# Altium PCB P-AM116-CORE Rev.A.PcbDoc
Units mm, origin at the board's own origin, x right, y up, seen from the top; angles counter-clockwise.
Board outline 129.17 x 91.46 mm, 2 copper layers (Top Layer, Bottom Layer); 0 components, 59 nets, 0 pads, 0 vias.
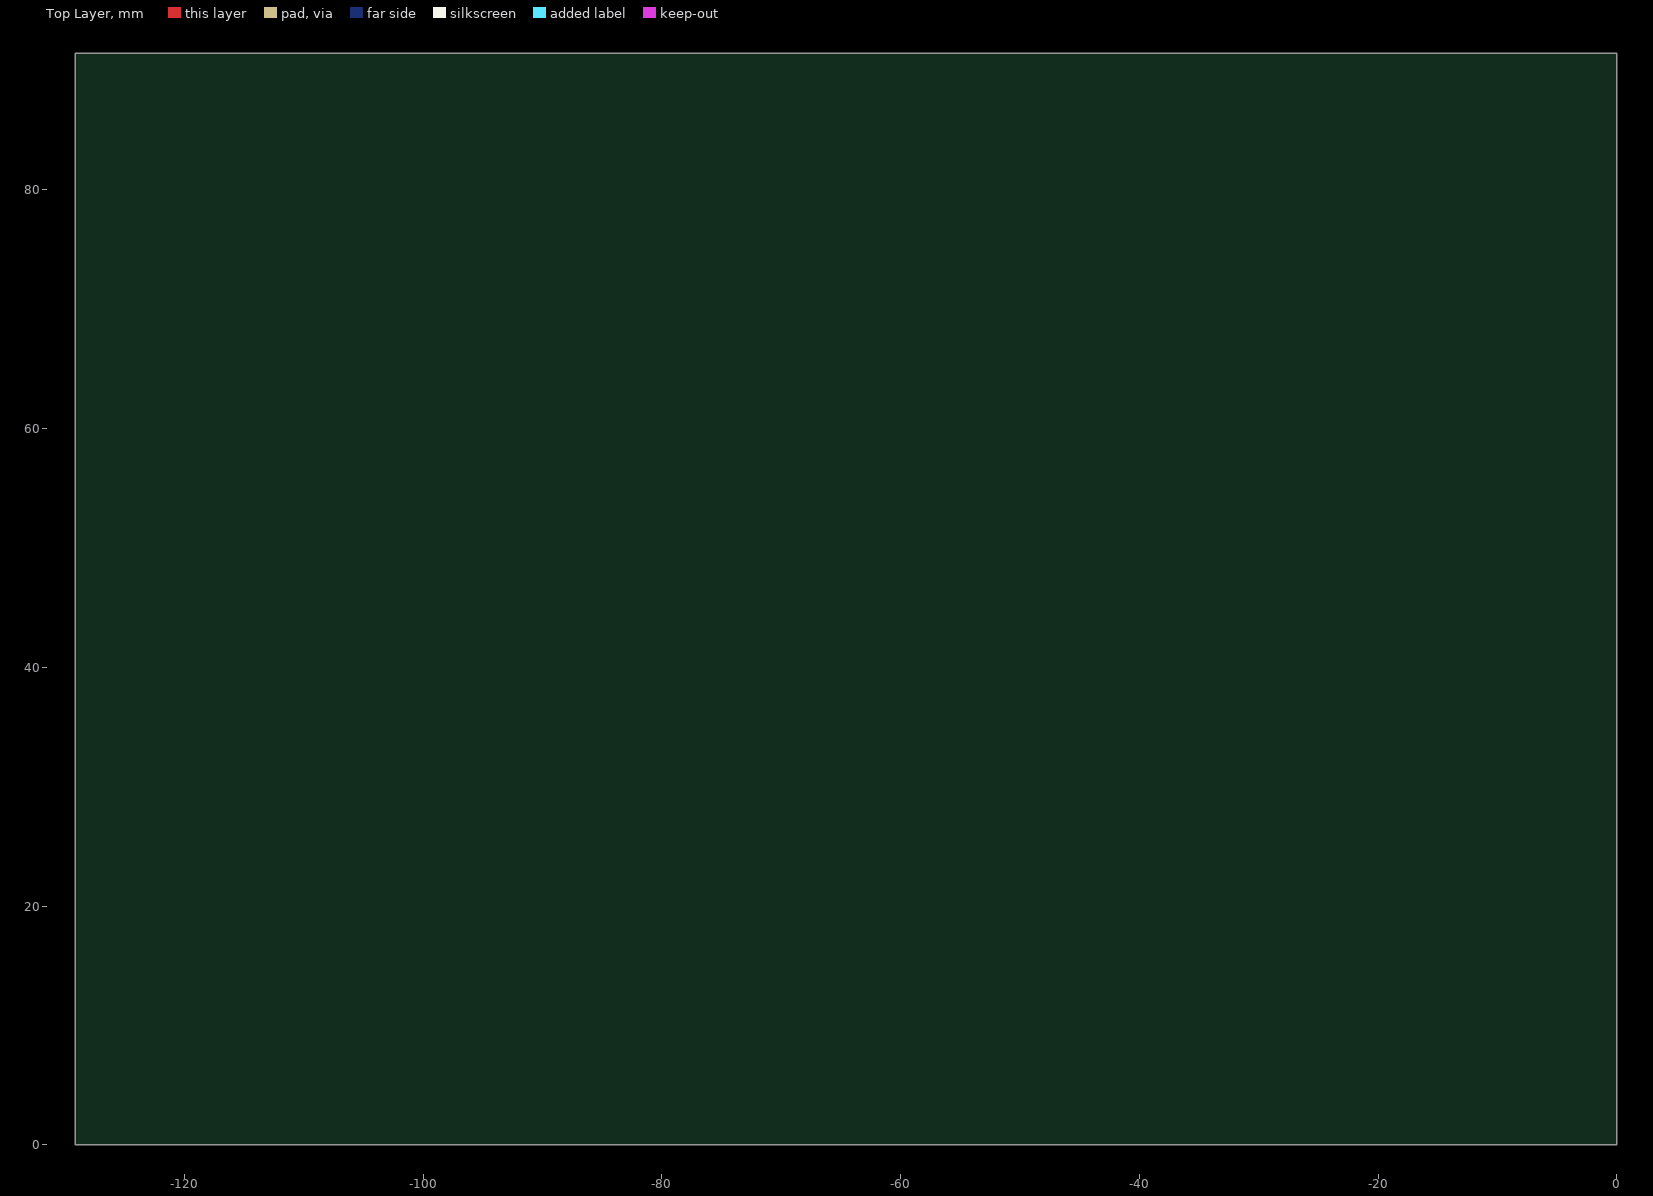
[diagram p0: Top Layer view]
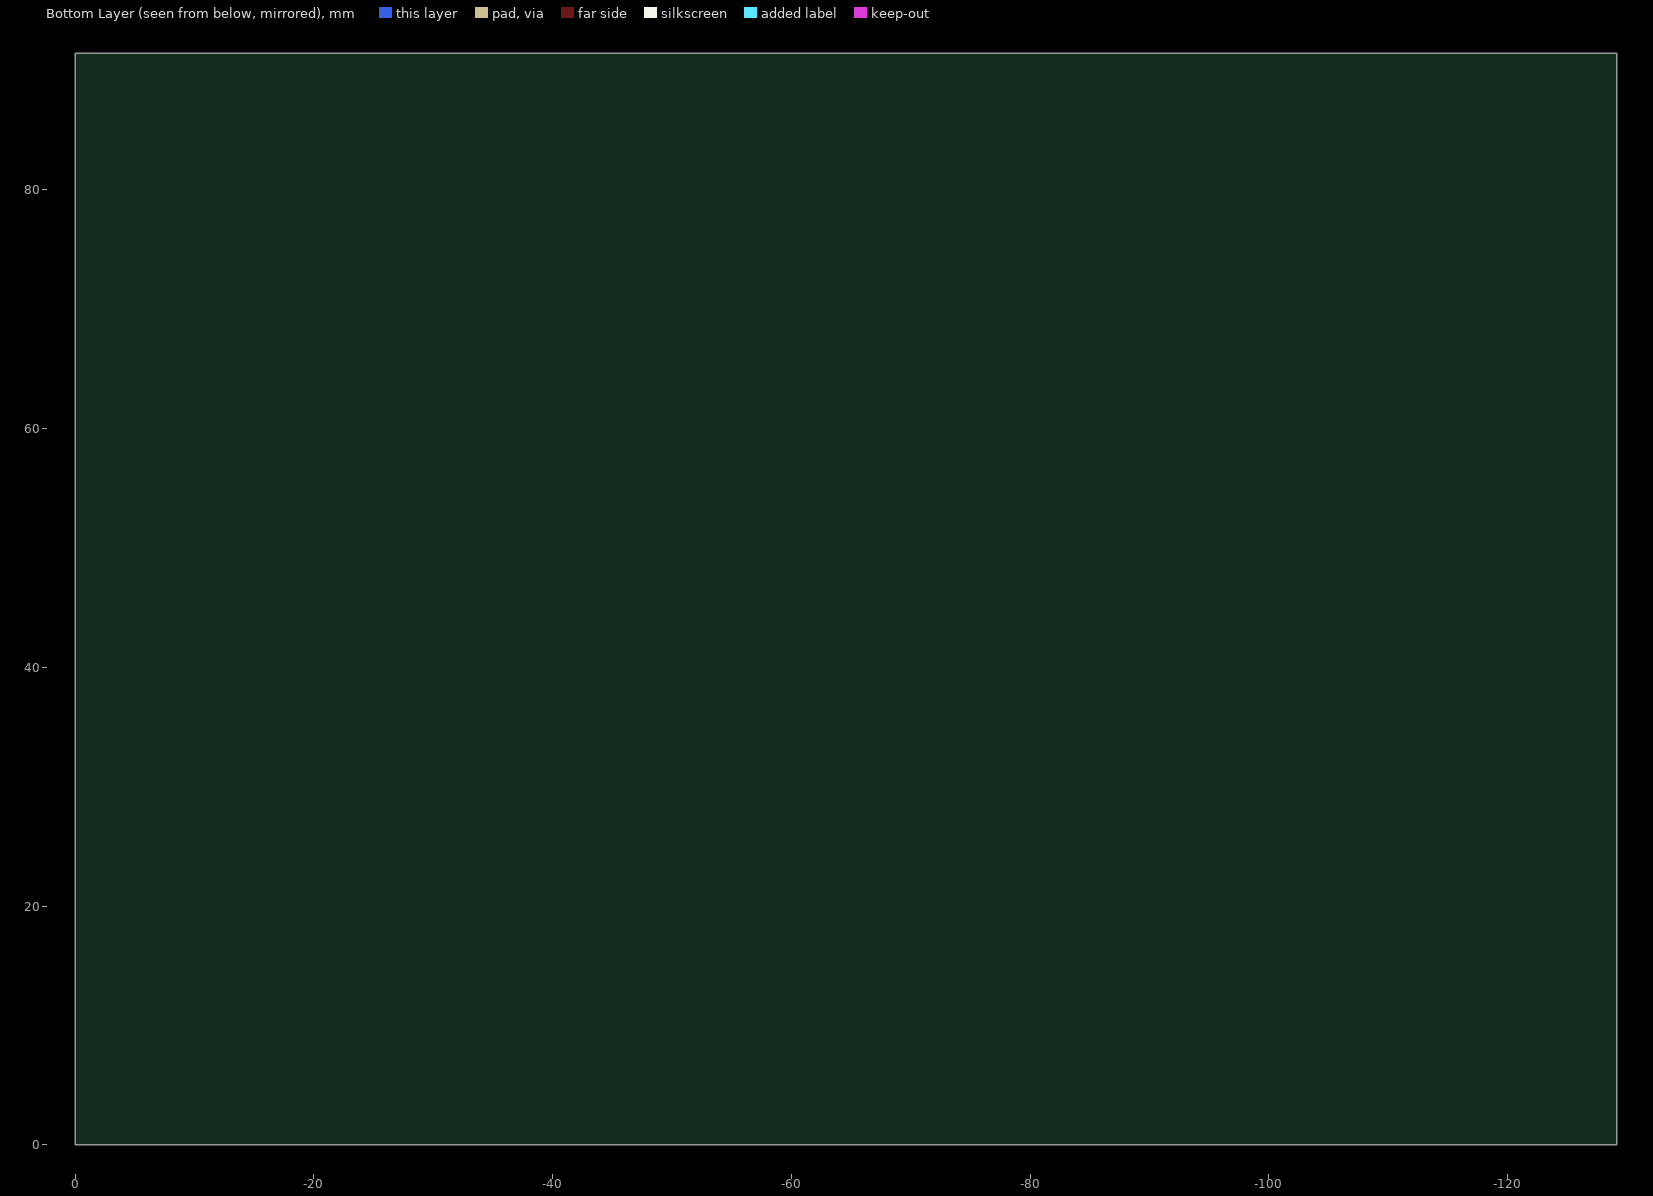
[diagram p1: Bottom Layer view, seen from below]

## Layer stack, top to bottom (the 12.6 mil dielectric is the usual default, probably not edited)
Top Solder: solder mask 0.0102, Solder Resist, Dk 3.5
Top Layer: signal copper 0.0356
Dielectric1: core 0.32, FR-4, Dk 4.8
Bottom Layer: signal copper 0.0356
Bottom Solder: solder mask 0.0102, Solder Resist, Dk 3.5

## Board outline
-129.165,0 -129.165,91.46 0,91.46 0,0

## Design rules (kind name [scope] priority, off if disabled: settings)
Clearance Clearance_Keepout [OnLayer('Keep-Out Layer')] p1: gap=0.508
Clearance Clearance_Manual [OnLayer('Bottom Layer') and IsSMTPin vs IsPadHoleValid>   (  HasFootprint('PAD-35/50') or   HasFootprint('HOLE-3.2') or  HasFootprint('HOLE-3.2 - Screw') or   HasFootprint('HOLE4.22-SMT') or   HasFootprint('Mou Hole-300D450W310H-SMD') or    HasFootprint('AW6748') or  HasFootprint('IDCS80P500W-20X2-F')  )] p2: gap=1.27
Clearance Clearance_Via2Via [IsVia vs IsVia] p3: gap=0.152
Clearance Clearance_Poly2All [InPoly] p4: gap=0.381
Clearance Clearance_TP [HasFootprint('PAD-40') vs HasFootprint('PAD-40')] p5: gap=1.27
Clearance [All] p6: gap=0.152
ComponentClearance [All] p1: gap=0 collisioncheckmode=3 verticalgap=0 showdistances=FALSE
DiffPairsRouting [All] p1: maxlimit=0.203 minlimit=0.203 mostfreqgap=0.203 toplayer_minwidth=0.14 toplayer_maxwidth=0.14 toplayer_prefwidth=0.14 bottomlayer_minwidth=0.14 bottomlayer_maxwidth=0.14 bottomlayer_prefwidth=0.14 maxuncoupledlength=12.7
HoleSize [All] p1: absolutevalues=TRUE maxlimit=25.4 minlimit=0.025 maxpercent=80.000 minpercent=20.000
MinimumSolderMaskSliver [All] p1: minsoldermaskwidth=0.025
PlaneClearance PlaneClearance_Full [IsVia] p1: clearance=0.229
PlaneClearance [All] p2: clearance=0.508
PlaneConnect PlaneConnect_Full [IsVia] p1: planeconnectstyle=Direct reliefexpansion=0.508 reliefentries=4 reliefconductorwidth=0.254 reliefairgap=0.254
PlaneConnect [All] p2: planeconnectstyle=Relief reliefexpansion=0.254 reliefentries=4 reliefconductorwidth=0.381 reliefairgap=0.254
PolygonConnect PolygonConnect_SMDHole [HasFootprint('Mou Hole-300D450W310H-SMD') or HasFootprint('Mou Hole-373D600H-SMD')] p1: connectstyle=Relief reliefconductorwidth=2.032 reliefentries=4 polygonreliefangle="45 Angle" airgapwidth=0.508
PolygonConnect PolygonConnect_Full [IsVia or   HasFootprint('PAD-40') or   HasFootprint('PAD-35/50') or  HasFootprint('HOLE-3.2') or   HasFootprint('HOLE-3.2 - Screw')] p2: connectstyle=Direct reliefconductorwidth=0.254 reliefentries=4 polygonreliefangle="90 Angle" airgapwidth=0.254
PolygonConnect [All] p3: connectstyle=Relief reliefconductorwidth=0.381 reliefentries=4 polygonreliefangle="90 Angle" airgapwidth=0.381
RoutingVias [All] p1: holewidth=0.305 width=0.508 viastyle="Through Hole" minholewidth=0.305 minwidth=0.508 maxholewidth=0.305 maxwidth=0.508
SilkToSilkClearance [All] p1: silktosilkclearance=0
SilkToSolderMaskClearance [IsPad] p1: minsilkscreentomaskgap=0 clearancetoexposedcopper=TRUE
SolderMaskExpansion [All] p1: expansion=0.102
Width [All] p1: maxlimit=2.54 minlimit=0.152 preferedwidth=0.152
22 further rules are at their usual default settings.

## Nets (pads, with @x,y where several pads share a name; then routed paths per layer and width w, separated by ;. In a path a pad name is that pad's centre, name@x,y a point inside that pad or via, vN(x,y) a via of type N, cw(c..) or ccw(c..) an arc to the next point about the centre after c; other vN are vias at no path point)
3.3V: 
3.3VA: 
3.3VA_MM32L: 
5V: 
5V/3.3VA_MICROP: 
ADC: 
ADC0/IO19_MICROP: 
ADC1/IO20_MICROP: 
AGND: 
BEEP: 
BOOT0: 
CS/GPIO7_MINIP: 
CTS/IO13_MICROP: 
DAC/IO21_MICROP: 
GPIO5_J5: 
GPIO6_J5: 
GPIO7_J5: 
GPIO8_J5: 
GPIO8_MINIP: 
GPIO9_J5: 
GPIO10_J5: 
GPIO11_J5: 
GPIO12_J5: 
GPIO13_J5: 
GPIO14_J5: 
GPIO14_MINIP: 
GPIO15_J5: 
GPIO16_J5: 
GPIO16_MINIP: 
GPIO17_J5: 
GPIO18_J5: 
GPIO18_MINIP: 
GPIO19_J5: 
GPIO20_J5: 
"IO 1_MICROP": 
"IO 2_MICROP": 
"IO 3_MICROP": 
LED0: 
LED1: 
LM75_SCL: 
LM75_SDA: 
MISO/GPIO9_MINIP: 
MOSI/GPIO15_MINIP: 
NetBZ1_1: 
NetC3_1: 
NetC4_1: 
NetC10_1: 
NetJ14_2: 
NetJ14_3: 
NetLED0_2: 
NetLED1_2: 
NetLED2_1: 
NetQ1_1: 
PA3/UART2_RX: 
PA5/SPI1_SCK: 
PWM2/IO7_MICROP: 
R\E\S\E\T\: 
SCL: 
SDA: 

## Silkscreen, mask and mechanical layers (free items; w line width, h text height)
Mechanical 1:
  lines w0.013: -129.165,4 -129.165,0 0,0 0,4 ; -129.165,87.46 -129.165,91.46 0,91.46 0,87.46
  lines w0.127: -131.705,3.998 -129.648,3.998 ; -131.705,45.728 -129.648,45.728 ; -131.705,87.458 -129.648,87.458 ; -130.333,3.49 -129.648,3.998 ; -130.333,4.506 -129.648,3.998 ; -130.333,45.22 -129.648,45.728 ; -130.333,46.236 -129.648,45.728 ; -130.333,86.95 -129.648,87.458 ; -130.333,87.966 -129.648,87.458 ; -65.077,93.726 -64.569,93.04 ; -64.569,95.098 -64.569,93.04 ; -64.061,93.726 -64.569,93.04 ; -129.165,45.73 -64.583,45.73 ; -129.165,45.73 -129.165,87.46 -64.583,87.46 ; -129.165,45.73 -129.165,4 -64.583,4 ; -129.165,45.73 -64.583,45.73 ; -64.583,4 0,4 0,45.73 ; -64.583,4 -64.583,45.73 ; -64.583,4 -64.583,45.73 ; -64.583,45.73 0,45.73 ; -64.583,45.73 -64.583,87.46 ; -64.583,45.73 -64.583,87.46 ; -64.583,45.73 0,45.73 ; -64.583,87.46 0,87.46 0,45.73
  text "VCUT" at -65.567,100.558 h1.52 r270
  text "VCUT" at -137.165,86.46 h1.52
  text "VCUT" at -137.293,45.118 h1.52
  text "VCUT" at -137.395,3.259 h1.52
Mechanical 2:
  drawing of 637 lines, arcs and shapes, not listed
  text "PCB加工工艺要求" at 70.723,109.689 h7.11
  text "mm x" at 50.327,104.965 h2.54
  text "mm" at 65.821,104.965 h2.54
  text "129.16" at 41.818,104.736 h2.54
  text "91.46" at 57.312,104.736 h2.54
  text "IPC-600E   IPC-6011/12" at 95.234,104.711 h2.54
  text "IPC-Ⅱ" at 129.143,104.686 h2.54
  text "IPC-Ⅲ" at 141.843,104.686 h2.54
  text "尺寸" at 27.764,104.257 h3.81
  text "验收标准" at 78.564,104.257 h3.81
  text "FR4 TG140" at 45.704,99.631 h2.54
  text "FR4 TG170" at 68.564,99.631 h2.54
  text "生益有胶材料" at 91.424,99.631 h2.54
  text "MEGTRON6" at 114.284,99.631 h2.54
  text "其他：" at 137.144,99.631 h2.54
  text "板材" at 27.728,99.172 h3.81
  text "单面" at 45.704,94.551 h2.54
  text "2" at 63.484,94.551 h2.54
  text "4" at 81.264,94.551 h2.54
  text "6" at 99.044,94.551 h2.54
  text "8" at 116.824,94.551 h2.54
  text "10" at 134.604,94.551 h2.54
  text "板层" at 27.728,94.087 h3.81
  text "0.4mm" at 45.704,89.471 h2.54
  text "0.6mm" at 59.674,89.471 h2.54
  text "0.8mm" at 73.644,89.471 h2.54
  text "1.0mm" at 87.614,89.471 h2.54
  text "1.2mm" at 101.584,89.471 h2.54
  text "1.4mm" at 115.554,89.471 h2.54
  text "1.6mm" at 129.524,89.471 h2.54
  text "1.8mm" at 143.494,89.471 h2.54
  text "2.0mm" at 157.464,89.471 h2.54
  text "板厚" at 27.728,89.001 h3.81
  text "1/2OZ" at 76.946,84.391 h2.54
  text "1OZ" at 89.646,84.391 h2.54
  text "2OZ" at 102.346,84.391 h2.54
  text "（完成铜厚）" at 51.63,84.067 h3.3
  text "外层" at 44.613,83.908 h3.81
  text "铜厚" at 27.724,83.876 h3.81
  text "白色" at 57.134,79.311 h2.54
  text "其他：" at 74.914,79.311 h2.54
  text "丝印颜色" at 27.724,78.816 h3.81
  text "绿色" at 57.134,74.231 h2.54
  text "黑色" at 74.914,74.231 h2.54
  text "红色" at 92.694,74.231 h2.54
  text "蓝色" at 110.474,74.231 h2.54
  text "黄色" at 128.254,74.231 h2.54
  text "其他：" at 146.034,74.231 h2.54
  text "（亮光）" at 41.45,73.911 h3.3
  text "阻焊颜色" at 27.724,73.73 h3.81
  text "沉镍金" at 57.134,69.151 h2.54
  text "无铅喷锡" at 74.914,69.151 h2.54
  text "电镀镍金" at 92.694,69.151 h2.54
  text "电镀软金" at 110.474,69.151 h2.54
  text "化学沉锡" at 128.254,69.151 h2.54
  text "光板" at 146.034,69.151 h2.54
  text "OSP" at 159.242,69.151 h2.54
  text "表面处理工艺" at 27.724,68.619 h3.81
  text "无" at 57.134,64.096 h2.54
  text "按键镀硬金" at 67.802,64.096 h2.54
  text "金手指" at 86.09,64.096 h2.54
  text "半孔工艺" at 103.616,64.096 h2.54
  text "FPCB补强" at 121.142,64.096 h2.54
  text "树脂塞孔" at 138.668,64.096 h2.54
  text "电镀填孔" at 156.194,64.096 h2.54
  text "特殊工艺" at 27.724,63.559 h3.81
  text "是" at 57.134,58.991 h2.54
  text "否" at 74.914,58.991 h2.54
  text "按文件" at 92.694,58.991 h2.54
  text "是否阻焊塞孔" at 27.728,58.463 h3.81
  text "非拼板" at 57.134,53.911 h2.54
  text "拼板" at 74.914,53.911 h2.54
  text "分成单板交货" at 92.694,53.911 h2.54
  text "交货方式" at 27.724,53.403 h3.81
  text "Gerber输出：英制、相对零点、抑制前导零、精度2:5" at 27.797,48.983 h3.05
  text "Ver 17.06.01" at 147.05,47.332 h3.05
  text "NC Drill输出：英制、相对零点、抑制前导零、精度2:4" at 27.797,45.427 h3.05
  text "其他说明" at 27.67,40.982 h3.81
  text "1." at 27.035,37.553 h3.05
  text "机械1层(*.GM1)为外形铣边；若存在工艺副边，请在副边上增加分流点" at 30.21,37.553 h3.05
  text "2." at 27.032,34.251 h3.05
  text "请用供应商UR认证标识(包括认证号，CTI等级，生产周期)替换放置在板上的UR标志；且保持其位置、方向一致；" at 30.21,34.251 h3.05
  text "R" at 139.71,32.613 h0.64
  text "94V-0" at 141.488,31.203 h1.17
  text "板内无UR标志的，若有工艺副边，可在副边上添加；否则禁止添加。标志样式如右 >>>" at 30.21,30.949 h3.05
  text "CTI>=175" at 137.525,29.044 h2.2
  text "3." at 27.035,27.647 h3.05
  text "若焊盘开窗与丝印油冲突，焊盘处需将丝印油掏开，不允许上盘" at 30.21,27.647 h3.05
  text "4." at 27.035,24.599 h3.05
  text "若存在V-CUT，无特别说明时，须为双面V-CUT，角度30（+-5℃），余量按以下表格执行" at 30.21,24.599 h3.05
  text "PCB厚度（mm）" at 41.158,20.154 h3.05
  text "筋厚" at 32.649,19.773 h3.05
  text "（余量）" at 31.379,16.725 h3.05
  text "0.6" at 41.158,16.598 h3.05
  text "0.8" at 47.244,16.598 h3.05
  text "1" at 54.77,16.598 h3.05
  text "1.2" at 59.446,16.598 h3.05
  text "1.6" at 65.542,16.598 h3.05
  text "2" at 72.781,16.598 h3.05
  text "2.5" at 77.718,16.598 h3.05
  text "3" at 84.973,16.598 h3.05
  text "0.16" at 40.399,13.106 h3.05
  text "0.2" at 47.257,13.106 h3.05
  text "0.3" at 53.353,13.106 h3.05
  text "0.3" at 59.344,13.106 h3.05
  text "0.4" at 65.453,13.106 h3.05
  text "0.5" at 71.645,13.106 h3.05
  text "0.5" at 77.737,13.106 h3.05
  text "0.5" at 83.066,13.106 h3.05
  text "最小值" at 31.252,13.042 h3.05
  text "0.32" at 40.409,9.613 h3.05
  text "0.4" at 47.25,9.613 h3.05
  text "0.45" at 52.587,9.613 h3.05
  text "0.5" at 59.337,9.613 h3.05
  text "0.6" at 65.516,9.613 h3.05
  text "0.7" at 71.652,9.613 h3.05
  text "0.8" at 77.741,9.613 h3.05
  text "0.8" at 83.833,9.613 h3.05
  text "最大值" at 31.252,9.486 h3.05
  text "5." at 27.035,5.168 h3.05
  text "PCB做完后，请高温烘烤进行应力释放，再整平（或重物压板烘烤），防止翘曲" at 30.21,5.168 h3.05
  text "未尽事项请参照我司《PCB质量补充协议》" at 30.083,1.485 h3.05
  text "6." at 27.035,1.358 h3.05
Drill Drawing:
  text ".Legend" at -128.93,103.53 h1.52

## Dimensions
0,0 to 0,91.46 on Mechanical 1
-129.165,0 to 0,0 on Mechanical 1

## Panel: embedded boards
"AM116-CORE Rev.A.PcbDoc" at 0,45.73, 1 rows x 1 columns, spacing 63.5 x 38.1, rotation 180
"AM116-CORE Rev.A.PcbDoc" at 0,87.46, 1 rows x 1 columns, spacing 63.5 x 38.1, rotation 180
"AM116-CORE Rev.A.PcbDoc" at -129.165,4, 1 rows x 1 columns, spacing 63.5 x 38.1, rotation 0
"AM116-CORE Rev.A.PcbDoc" at -129.165,45.73, 1 rows x 1 columns, spacing 63.5 x 38.1, rotation 0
